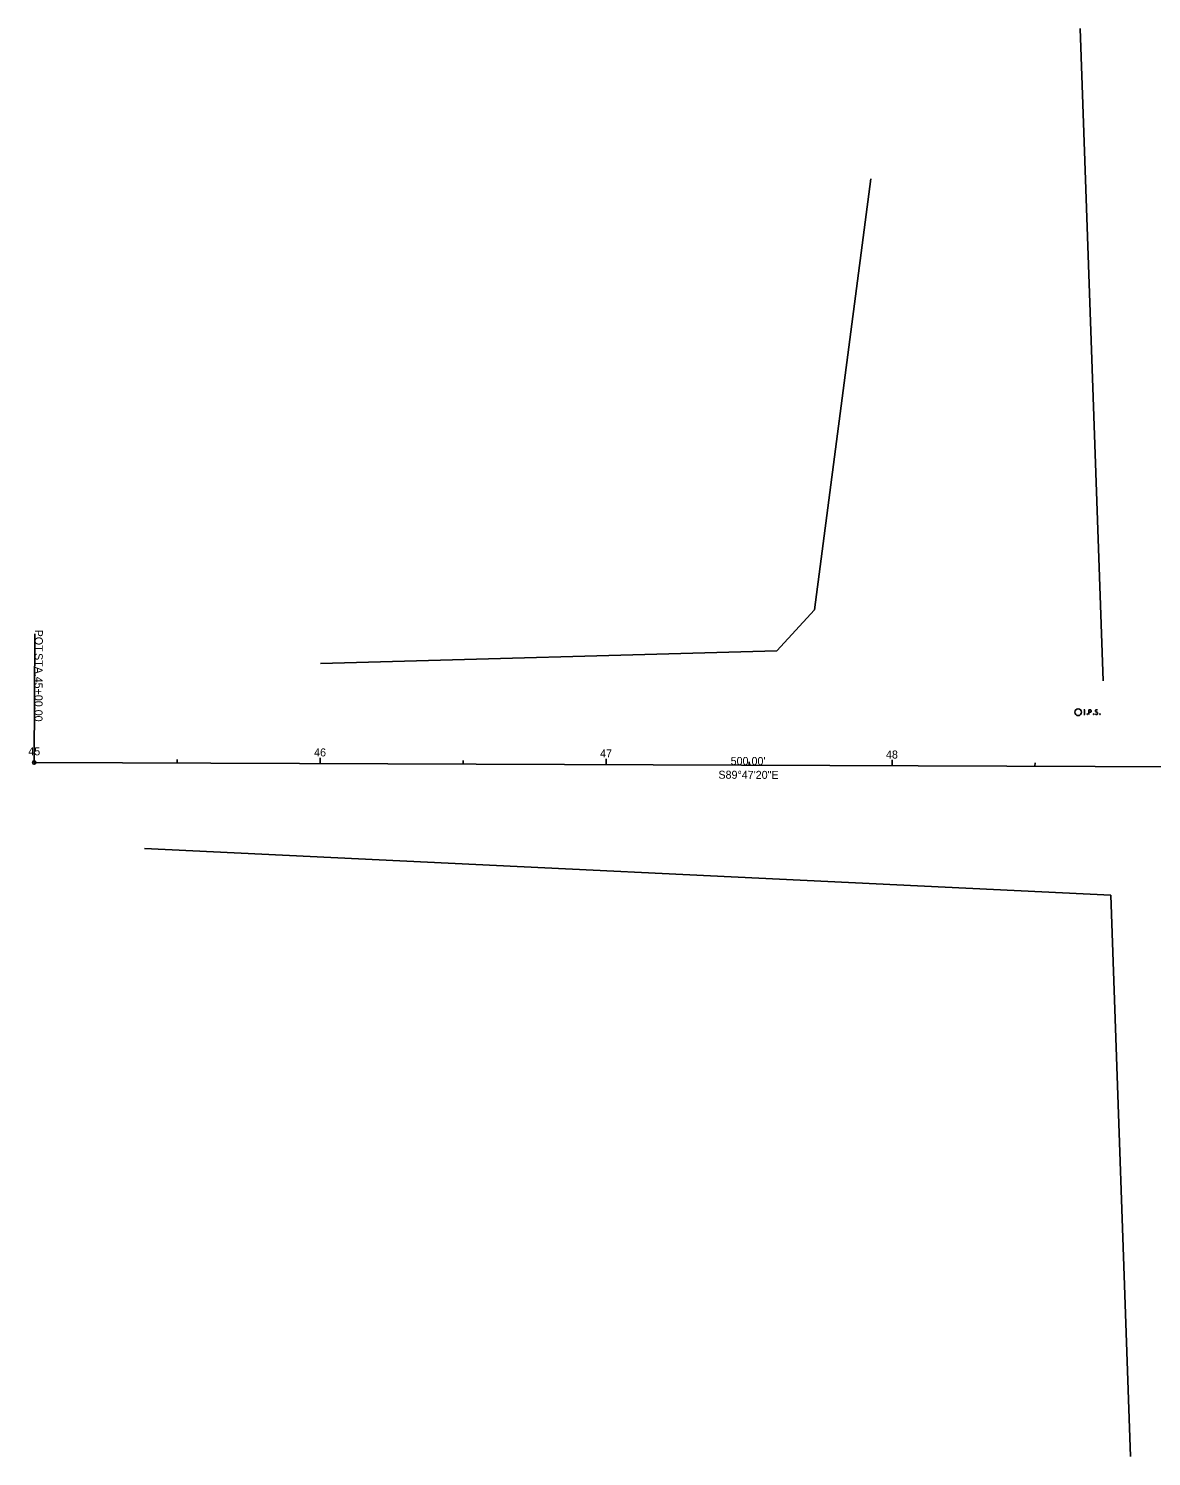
# Model space of a CAD drawing. Extents: x 146022 to 147490, y 436269 to 440659.
# Drawn here: x 146485.1 to 146877.9, y 438387.5 to 438887.2 of the extents above; entities that cross this region are included whole.
import ezdxf

# ---------------------------------------------------------------- set-up
doc = ezdxf.new("R2010")
doc.units = 0
for name, color, linetype in [('GE_X_Alignment', 7, 'Continuous'), ('GE_X_Alignment_100_Bearings', 7, 'Continuous'), ('GE_X_Alignment_100_Cardinal_Points', 7, 'Continuous'), ('GE_X_Alignment_100_Distances', 7, 'Continuous'), ('GE_X_Alignment_100_Stations', 7, 'Continuous'), ('RW_X_Esmt_SH', 7, 'Continuous'), ('RW_X_Fee_WL', 7, 'Continuous'), ('SV_P_Mon_Cells_Set', 7, 'Continuous')]:
    doc.layers.add(name, color=color, linetype=linetype)

msp = doc.modelspace()

# ---------------------------------------------------------------- linework, layer by layer
at = {"layer": 'GE_X_Alignment'}
msp.add_line((146487.13, 438630.33), (146987.13, 438628.49), dxfattribs=at)
at = {"layer": 'GE_X_Alignment_100_Cardinal_Points'}
msp.add_line((146487.13, 438630.33), (146487.3, 438675.33), dxfattribs=at)
msp.add_circle((146487.13, 438630.33), 0.6, dxfattribs=at)
at = {"layer": 'GE_X_Alignment_100_Stations'}
for p, q in [((146487.13, 438630.33), (146487.14, 438632.33)), ((146537.13, 438630.15), (146537.14, 438631.35)), ((146587.13, 438629.96), (146587.14, 438631.96)), ((146637.13, 438629.78), (146637.14, 438630.98)), ((146687.13, 438629.59), (146687.14, 438631.59)), ((146737.13, 438629.41), (146737.14, 438630.61)), ((146787.13, 438629.22), (146787.14, 438631.22)), ((146837.13, 438629.04), (146837.14, 438630.24))]:
    msp.add_line(p, q, dxfattribs=at)
at = {"layer": 'RW_X_Esmt_SH'}
for p, q in [((146760.03, 438683.75), (146779.71, 438834.55)), ((146746.85, 438669.37), (146760.03, 438683.75)), ((146587.26, 438664.96), (146746.85, 438669.37)), ((146525.73, 438600.19), (146863.63, 438583.94))]:
    msp.add_line(p, q, dxfattribs=at)
at = {"layer": 'RW_X_Fee_WL'}
for p, q in [((146860.97, 438658.95), (146852.89, 438887.17)), ((146870.59, 438387.48), (146863.63, 438583.94))]:
    msp.add_line(p, q, dxfattribs=at)
at = {"layer": 'SV_P_Mon_Cells_Set'}
for points in [[(146854.25, 438648.74), (146854.6, 438648.74)], [(146854.25, 438647.14), (146854.6, 438647.14)], [(146854.42, 438647.14), (146854.42, 438648.74)], [(146855.38, 438647.35), (146855.44, 438647.35), (146855.47, 438647.32), (146855.5, 438647.27), (146855.5, 438647.21), (146855.47, 438647.16), (146855.44, 438647.14), (146855.38, 438647.14), (146855.35, 438647.16), (146855.31, 438647.21), (146855.31, 438647.27), (146855.35, 438647.32), (146855.38, 438647.35)], [(146855.99, 438647.14), (146855.99, 438648.74), (146856.52, 438648.74), (146856.57, 438648.72), (146856.65, 438648.7), (146856.68, 438648.67), (146856.71, 438648.65), (146856.76, 438648.58), (146856.79, 438648.52), (146856.81, 438648.42), (146856.81, 438648.27), (146856.8, 438648.22), (146856.78, 438648.14), (146856.74, 438648.05), (146856.69, 438648.02), (146856.66, 438647.99), (146856.6, 438647.97), (146856.52, 438647.95), (146855.99, 438647.95)], [(146857.63, 438647.35), (146857.68, 438647.35), (146857.72, 438647.32), (146857.75, 438647.27), (146857.75, 438647.21), (146857.72, 438647.16), (146857.68, 438647.14), (146857.63, 438647.14), (146857.6, 438647.16), (146857.56, 438647.21), (146857.56, 438647.27), (146857.6, 438647.32), (146857.63, 438647.35)], [(146859, 438648.62), (146858.97, 438648.65), (146858.94, 438648.67), (146858.84, 438648.71), (146858.72, 438648.74), (146858.63, 438648.74), (146858.6, 438648.74), (146858.46, 438648.7), (146858.33, 438648.62), (146858.26, 438648.52), (146858.24, 438648.42), (146858.24, 438648.34), (146858.26, 438648.24), (146858.35, 438648.16), (146858.95, 438647.78), (146859.01, 438647.73), (146859.03, 438647.68), (146859.05, 438647.6), (146859.05, 438647.53), (146859.04, 438647.45), (146859.03, 438647.4), (146859.01, 438647.34), (146858.99, 438647.29), (146858.96, 438647.25), (146858.93, 438647.21), (146858.9, 438647.19), (146858.85, 438647.16), (146858.82, 438647.15), (146858.72, 438647.14), (146858.57, 438647.14), (146858.47, 438647.16), (146858.32, 438647.25), (146858.24, 438647.32)], [(146859.81, 438647.35), (146859.87, 438647.35), (146859.9, 438647.32), (146859.93, 438647.27), (146859.93, 438647.21), (146859.9, 438647.16), (146859.87, 438647.14), (146859.81, 438647.14), (146859.78, 438647.16), (146859.75, 438647.21), (146859.75, 438647.27), (146859.78, 438647.32), (146859.81, 438647.35)]]:
    msp.add_lwpolyline(points, dxfattribs=at)
msp.add_circle((146852.23, 438647.93), 1.2, dxfattribs=at)

# ---------------------------------------------------------------- texts
at = {"layer": 'GE_X_Alignment_100_Bearings'}
msp.add_text('S89°47\'20"E', height=2.8, rotation=359.7889, dxfattribs=at).set_placement((146726.41, 438624.65))
at = {"layer": 'GE_X_Alignment_100_Cardinal_Points'}
for s, p in [('POT', (146487.34, 438676.81)), (' STA. ', (146487.31, 438669.68)), ('45+00.00', (146487.28, 438660.36))]:
    msp.add_text(s, height=2.8, rotation=269.7889, dxfattribs=at).set_placement(p)
at = {"layer": 'GE_X_Alignment_100_Distances'}
msp.add_text("500.00'", height=2.8, rotation=359.7889, dxfattribs=at).set_placement((146730.69, 438629.47))
at = {"layer": 'GE_X_Alignment_100_Stations'}
for s, p in [('45', (146485.05, 438632.84)), ('46', (146585, 438632.47)), ('47', (146685.02, 438632.1)), ('48', (146785.01, 438631.73))]:
    msp.add_text(s, height=2.8, rotation=359.7889, dxfattribs=at).set_placement(p)

doc.saveas('drawing.dxf')
